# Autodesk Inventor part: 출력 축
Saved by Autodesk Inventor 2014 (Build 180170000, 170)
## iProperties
Created: 2026-04
Part Number: 출력 축
Material: 강철, 탄소
Document SubType Name: Modeling
Designer: dg
Density: 7.87 g/cm^3
Appearance: 반연마
Mass: 512.094 g
Surface Area: 123.954 cm^2
Volume: 65.0691 cm^3
Author: jhkim
Creation Date: 2026-03-27
Sending System: Autodesk Inventor 2026
Preprocessor: ST-DEVELOPER v20.1
Author: dg
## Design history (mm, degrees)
node "출력 축1"
node "솔리드1"
node "기준1"
